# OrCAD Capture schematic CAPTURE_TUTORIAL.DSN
size A; title: Capture Walkthrough; rev: A; company: EMA Design Automation; note: EMA-12345678; note: 225 Tech park Dr; note: Rochester, NY
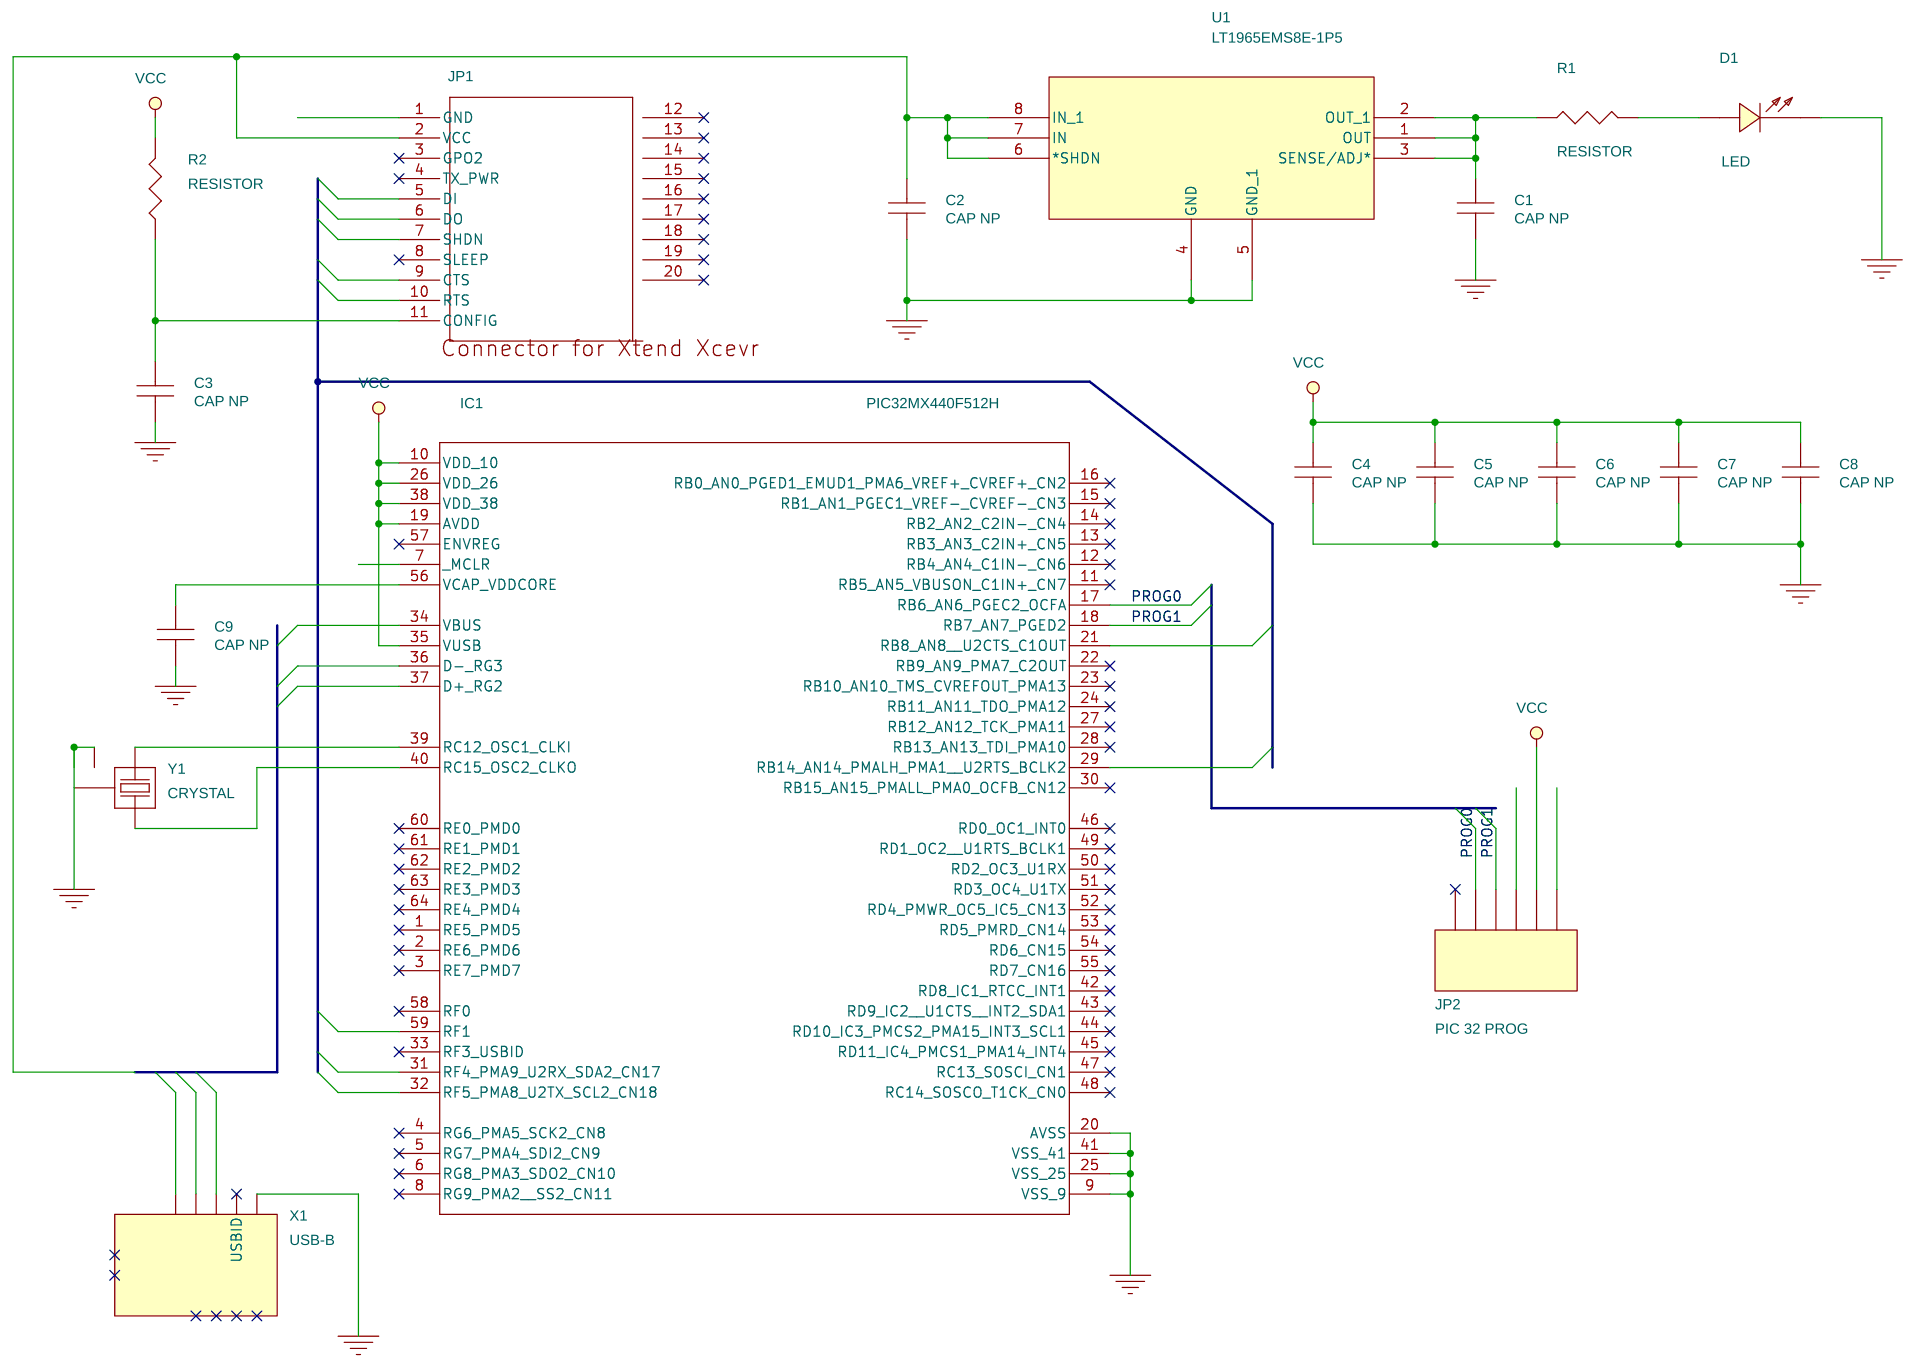
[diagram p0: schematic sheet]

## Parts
C1  CAP NP
C2  CAP NP
C3  CAP NP
C4  CAP NP
C5  CAP NP
C6  CAP NP
C7  CAP NP
C8  CAP NP
C9  CAP NP
D1  LED
IC1  PIC32MX440F512H  [sqfp-s-10x10-64]
JP1  XTEND-DIGI-MODEM  [xtend-digi-modem]
JP2  PIC 32 PROG  [1x06_lock]
R1  RESISTOR
R2  RESISTOR
U1  LT1965EMS8E-1P5  [MSOP_8_ADI]
X1  USB-B  [USB-MICROB]
Y1  CRYSTAL  [crystal-smd]

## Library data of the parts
C1-C9 = CAP_NP
D1 = LED
IC1 = PIC32MX440F512H
JP1 = XTEND-DIGI-MODEM
JP2 = M06_LOCK
R1 R2 = RESISTOR
U1 = LT1965EMS8E-1P5_1: Distributor Id: Digi-Key; Distributor Part Number: 2156-LT1965EMS8E-1.5-600060-ND; Manufacturer Name: Analog Devices Inc; Manufacturer Part Number: LT1965EMS8E-1.5; Part Number: LT1965EMS8E-1.5; Source Id: UL
X1 = USB-MICROB
Y1 = CRYSTAL

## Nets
GND: C1.2 C2.2 C3.2 C4.2 C5.2 C6.2 C7.2 C8.2 C9.2 D1.1(CATHODE) IC1.9(VSS) IC1.20(AVSS) IC1.25(VSS) IC1.41(VSS) U1.4(GND) U1.5(GND_1) X1.GND Y1.2(GND) Y1.4(GND)
VCC: C4.1 C5.1 C6.1 C7.1 C8.1 IC1.10(VDD) IC1.19(AVDD) IC1.26(VDD) IC1.35(VUSB) IC1.38(VDD) JP2.2 R2.2
PROG0: IC1.17(RB6_AN6_PGEC2_OCFA) JP2.5
PROG1: IC1.18(RB7_AN7_PGED2) JP2.4
N01813: C2.1 JP1.2(VCC) U1.6(*SHDN) U1.7(IN) U1.8(IN_1)
N01895: C1.1 R1.1 U1.1(OUT) U1.2(OUT_1) U1.3(SENSE/ADJ*)
N01899: D1.2(ANODE) R1.2
N02098: IC1.39(RC12_OSC1_CLKI) Y1.1
N02102: IC1.40(RC15_OSC2_CLKO) Y1.3
N02114: C9.1 IC1.56(VCAP_VDDCORE)
N02189: C3.1 JP1.11(CONFIG) R2.1

Not connected (* = marked no-connect by the designer): IC1 1(RE5_PMD5)* 2(RE6_PMD6)* 3(RE7_PMD7)* 4(RG6_PMA5_SCK2_CN8)* 5(RG7_PMA4_SDI2_CN9)* 6(RG8_PMA3_SDO2_CN10)* 7(_MCLR) 8(RG9_PMA2__SS2_CN11)* 11(RB5_AN5_VBUSON_C1IN+_CN7)* 12(RB4_AN4_C1IN-_CN6)* 13(RB3_AN3_C2IN+_CN5)* 14(RB2_AN2_C2IN-_CN4)* 15(RB1_AN1_PGEC1_VREF-_CVREF-_CN3)* 16(RB0_AN0_PGED1_EMUD1_PMA6_VREF+_CVREF+_CN2)* 21(RB8_AN8__U2CTS_C1OUT) 22(RB9_AN9_PMA7_C2OUT)* 23(RB10_AN10_TMS_CVREFOUT_PMA13)* 24(RB11_AN11_TDO_PMA12)* 27(RB12_AN12_TCK_PMA11)* 28(RB13_AN13_TDI_PMA10)* 29(RB14_AN14_PMALH_PMA1__U2RTS_BCLK2) 30(RB15_AN15_PMALL_PMA0_OCFB_CN12)* 31(RF4_PMA9_U2RX_SDA2_CN17) 32(RF5_PMA8_U2TX_SCL2_CN18) 33(RF3_USBID)* 34(VBUS) 36(D-_RG3) 37(D+_RG2) 42(RD8_IC1_RTCC_INT1)* 43(RD9_IC2__U1CTS__INT2_SDA1)* 44(RD10_IC3_PMCS2_PMA15_INT3_SCL1)* 45(RD11_IC4_PMCS1_PMA14_INT4)* 46(RD0_OC1_INT0)* 47(RC13_SOSCI_CN1)* 48(RC14_SOSCO_T1CK_CN0)* 49(RD1_OC2__U1RTS_BCLK1)* 50(RD2_OC3_U1RX)* 51(RD3_OC4_U1TX)* 52(RD4_PMWR_OC5_IC5_CN13)* 53(RD5_PMRD_CN14)* 54(RD6_CN15)* 55(RD7_CN16)* 57(ENVREG)* 58(RF0)* 59(RF1) 60(RE0_PMD0)* 61(RE1_PMD1)* 62(RE2_PMD2)* 63(RE3_PMD3)* 64(RE4_PMD4)*; JP1 1(GND) 3(GPO2)* 4(TX_PWR)* 5(DI) 6(DO) 7(SHDN) 8(SLEEP)* 9(CTS) 10(RTS) 12* 13* 14* 15* 16* 17* 18* 19* 20*; JP2 1 3 6*; X1 D+ D- ID(USBID)* MT1* MT2* MT3* MT4* P_1* P_2* VBUS
